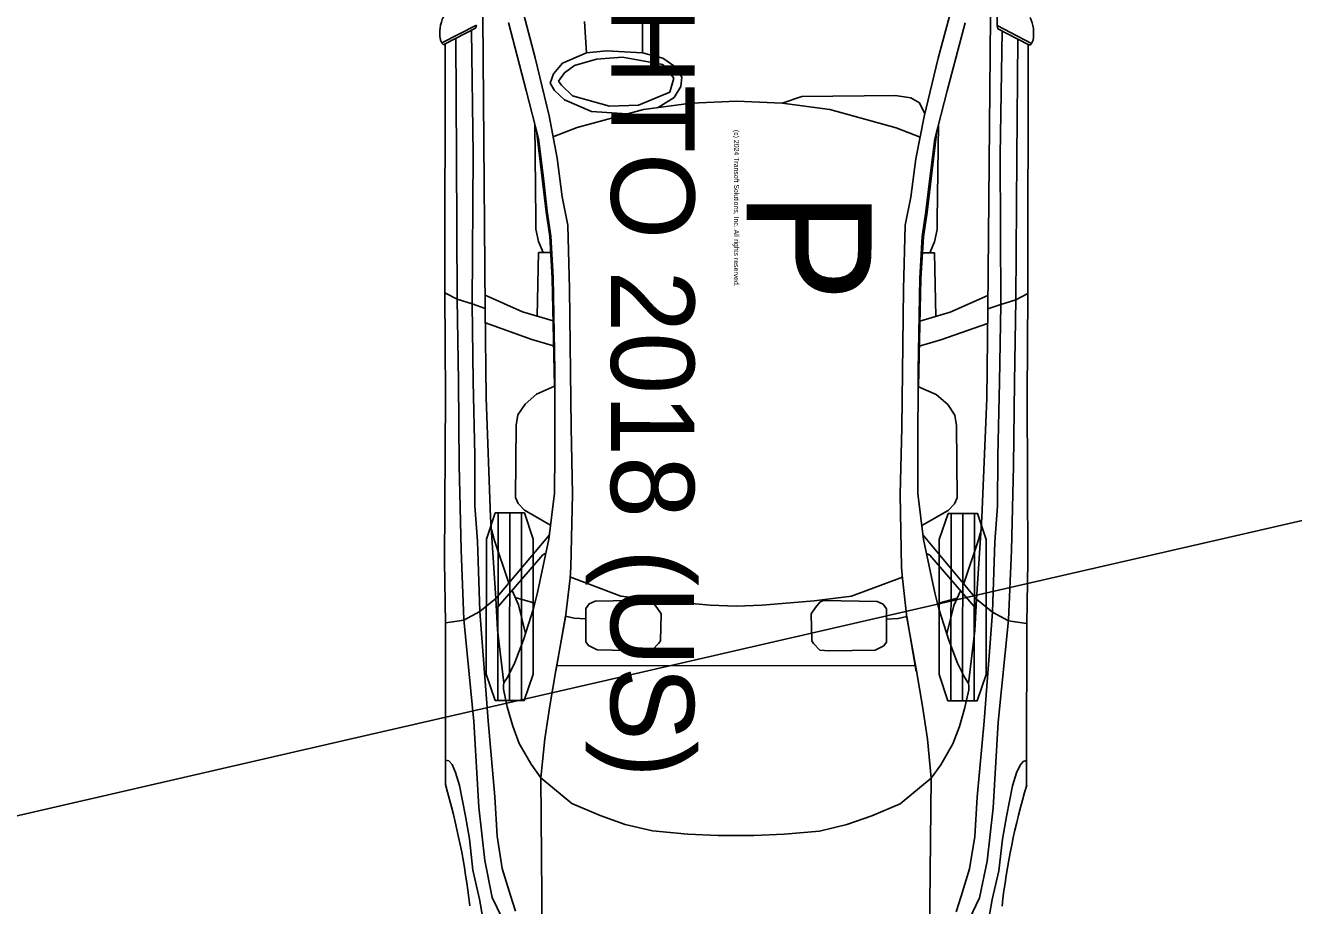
# Model space of a CAD drawing. Extents: x 17465868 to 18455672, y 7253752 to 7478845.
# Drawn here: x 18455110.2 to 18455125.43, y 7478342.35 to 7478352.92 of the extents above; entities that cross this region are included whole.
import ezdxf

# ---------------------------------------------------------------- set-up
doc = ezdxf.new("R2010")
doc.units = 0
doc.layers.add('Clinton 225 CL Girders', color=7, linetype='Continuous')
doc.layers.add('Dallas 126 CL Girder', color=7, linetype='Continuous')

msp = doc.modelspace()

# ---------------------------------------------------------------- linework, layer by layer
at = {"layer": 'Clinton 225 CL Girders'}
for p, q in [((18455116.144, 7478353.217), (18455116.324, 7478352.533)), ((18455121.345, 7478353.212), (18455121.164, 7478352.528)), ((18455115.697, 7478353.028), (18455115.726, 7478349.524)), ((18455116.217, 7478352.143), (18455116.004, 7478352.959)), ((18455116.94, 7478352.593), (18455116.917, 7478352.97)), ((18455117.615, 7478352.995), (18455117.615, 7478352.593)), ((18455121.792, 7478353.022), (18455121.757, 7478349.519)), ((18455121.87, 7478353.033), (18455121.87, 7478352.921)), ((18455115.204, 7478352.712), (18455115.619, 7478352.927)), ((18455115.61, 7478352.888), (18455115.244, 7478352.701)), ((18455115.58, 7478351.371), (18455115.56, 7478352.863)), ((18455115.619, 7478352.927), (18455115.61, 7478352.888)), ((18455121.485, 7478352.953), (18455121.271, 7478352.138)), ((18455121.87, 7478352.921), (18455121.879, 7478352.882)), ((18455122.285, 7478352.706), (18455121.87, 7478352.921)), ((18455121.879, 7478352.882), (18455122.244, 7478352.694)), ((18455121.906, 7478351.365), (18455121.929, 7478352.857)), ((18455115.186, 7478352.753), (18455115.204, 7478352.712)), ((18455115.207, 7478352.706), (18455115.213, 7478352.7)), ((18455115.244, 7478352.701), (18455115.241, 7478349.712)), ((18455115.371, 7478352.765), (18455115.38, 7478351.338)), ((18455122.106, 7478351.332), (18455122.118, 7478352.759)), ((18455122.241, 7478349.705), (18455122.244, 7478352.694)), ((18455122.275, 7478352.693), (18455122.281, 7478352.7)), ((18455122.285, 7478352.706), (18455122.302, 7478352.746)), ((18455116.324, 7478352.533), (18455116.491, 7478351.836)), ((18455116.651, 7478352.468), (18455116.94, 7478352.593)), ((18455116.796, 7478352.443), (18455117.061, 7478352.518)), ((18455116.94, 7478352.593), (18455117.181, 7478352.618)), ((18455117.061, 7478352.518), (18455117.374, 7478352.543)), ((18455117.181, 7478352.618), (18455117.615, 7478352.593)), ((18455117.374, 7478352.543), (18455117.856, 7478352.454)), ((18455117.615, 7478352.593), (18455117.856, 7478352.529)), ((18455117.856, 7478352.529), (18455118, 7478352.429)), ((18455121.164, 7478352.528), (18455120.996, 7478351.831)), ((18455116.543, 7478352.342), (18455116.651, 7478352.468)), ((18455116.603, 7478352.254), (18455116.675, 7478352.355)), ((18455116.675, 7478352.355), (18455116.796, 7478352.443)), ((18455117.856, 7478352.454), (18455117.988, 7478352.291)), ((18455118, 7478352.429), (18455118.084, 7478352.303)), ((18455116.506, 7478352.229), (18455116.543, 7478352.342)), ((18455116.555, 7478352.141), (18455116.506, 7478352.229)), ((18455116.639, 7478352.204), (18455116.603, 7478352.254)), ((18455116.771, 7478352.078), (18455116.639, 7478352.204)), ((18455117.988, 7478352.291), (18455117.942, 7478352.123)), ((18455118.084, 7478352.303), (18455118.072, 7478352.19)), ((18455116.363, 7478351.564), (18455116.217, 7478352.143)), ((18455116.675, 7478352.028), (18455116.555, 7478352.141)), ((18455117.217, 7478351.952), (18455116.771, 7478352.078)), ((18455117.942, 7478352.123), (18455117.566, 7478351.964)), ((18455117.995, 7478352.056), (18455117.803, 7478351.939)), ((18455118.072, 7478352.19), (18455117.995, 7478352.056)), ((18455119.289, 7478351.99), (18455119.526, 7478352.069)), ((18455119.526, 7478352.069), (18455120.646, 7478352.08)), ((18455120.646, 7478352.08), (18455120.834, 7478352.055)), ((18455120.834, 7478352.055), (18455120.94, 7478351.993)), ((18455121.271, 7478352.138), (18455121.123, 7478351.559)), ((18455117, 7478351.89), (18455116.675, 7478352.028)), ((18455117.624, 7478351.915), (18455116.829, 7478351.698)), ((18455117.566, 7478351.964), (18455117.217, 7478351.952)), ((18455118.199, 7478351.991), (18455117.624, 7478351.915)), ((18455118.744, 7478352.012), (18455118.199, 7478351.991)), ((18455119.289, 7478351.99), (18455118.744, 7478352.012)), ((18455119.863, 7478351.913), (18455119.289, 7478351.99)), ((18455120.657, 7478351.694), (18455119.863, 7478351.913)), ((18455120.94, 7478351.993), (18455121.003, 7478351.863)), ((18455116.491, 7478351.836), (18455116.59, 7478351.327)), ((18455117.431, 7478351.863), (18455117, 7478351.89)), ((18455120.996, 7478351.831), (18455120.896, 7478351.322)), ((18455116.333, 7478350.594), (18455116.319, 7478351.738)), ((18455116.455, 7478350.685), (18455116.339, 7478351.66)), ((18455116.829, 7478351.698), (18455116.547, 7478351.589)), ((18455120.947, 7478351.582), (18455120.657, 7478351.694)), ((18455121.029, 7478350.681), (18455121.148, 7478351.656)), ((18455121.151, 7478350.589), (18455121.167, 7478351.733)), ((18455116.423, 7478351.09), (18455116.363, 7478351.564)), ((18455121.123, 7478351.559), (18455121.062, 7478351.085)), ((18455115.38, 7478351.338), (18455115.389, 7478349.635)), ((18455115.568, 7478349.579), (18455115.58, 7478351.371)), ((18455116.59, 7478351.327), (18455116.65, 7478350.866)), ((18455120.896, 7478351.322), (18455120.835, 7478350.862)), ((18455121.915, 7478349.573), (18455121.906, 7478351.365)), ((18455122.094, 7478349.628), (18455122.106, 7478351.332)), ((18455116.469, 7478350.692), (18455116.423, 7478351.09)), ((18455121.062, 7478351.085), (18455121.015, 7478350.688)), ((18455116.65, 7478350.866), (18455116.718, 7478350.525)), ((18455120.835, 7478350.862), (18455120.767, 7478350.522)), ((18455116.499, 7478350.386), (18455116.455, 7478350.685)), ((18455116.512, 7478350.393), (18455116.469, 7478350.692)), ((18455121.015, 7478350.688), (18455120.972, 7478350.389)), ((18455120.985, 7478350.382), (18455121.029, 7478350.681)), ((18455116.333, 7478350.476), (18455116.333, 7478350.594)), ((18455116.718, 7478350.525), (18455116.737, 7478349.761)), ((18455121.151, 7478350.472), (18455121.151, 7478350.589)), ((18455116.364, 7478350.329), (18455116.333, 7478350.476)), ((18455116.529, 7478349.887), (18455116.499, 7478350.386)), ((18455116.541, 7478349.894), (18455116.512, 7478350.393)), ((18455120.767, 7478350.522), (18455120.746, 7478349.757)), ((18455120.972, 7478350.389), (18455120.942, 7478349.889)), ((18455120.954, 7478349.883), (18455120.985, 7478350.382)), ((18455121.12, 7478350.325), (18455121.151, 7478350.472)), ((18455116.42, 7478350.197), (18455116.364, 7478350.329)), ((18455121.064, 7478350.192), (18455121.12, 7478350.325)), ((18455116.349, 7478349.43), (18455116.364, 7478350.197)), ((18455116.364, 7478350.197), (18455116.507, 7478350.197)), ((18455121.12, 7478350.192), (18455120.977, 7478350.193)), ((18455121.133, 7478349.426), (18455121.12, 7478350.192)), ((18455116.555, 7478348.589), (18455116.529, 7478349.887)), ((18455116.56, 7478348.782), (18455116.541, 7478349.894)), ((18455116.737, 7478349.761), (18455116.755, 7478348.099)), ((18455120.942, 7478349.889), (18455120.921, 7478348.778)), ((18455120.926, 7478348.584), (18455120.954, 7478349.883)), ((18455115.241, 7478349.712), (18455115.389, 7478349.635)), ((18455115.241, 7478349.712), (18455115.248, 7478348.473)), ((18455115.389, 7478349.635), (18455115.404, 7478348.646)), ((18455115.389, 7478349.635), (18455115.568, 7478349.579)), ((18455115.725, 7478349.684), (18455116.174, 7478349.483)), ((18455120.746, 7478349.757), (18455120.725, 7478348.095)), ((18455121.758, 7478349.678), (18455121.308, 7478349.478)), ((18455122.094, 7478349.628), (18455121.915, 7478349.573)), ((18455122.077, 7478348.64), (18455122.094, 7478349.628)), ((18455122.241, 7478349.705), (18455122.094, 7478349.628)), ((18455122.232, 7478348.466), (18455122.241, 7478349.705)), ((18455115.581, 7478348.646), (18455115.568, 7478349.579)), ((18455115.568, 7478349.579), (18455115.726, 7478349.524)), ((18455115.726, 7478349.524), (18455115.736, 7478348.449)), ((18455116.174, 7478349.483), (18455116.539, 7478349.373)), ((18455121.308, 7478349.478), (18455120.943, 7478349.369)), ((18455121.757, 7478349.519), (18455121.745, 7478348.443)), ((18455121.915, 7478349.573), (18455121.757, 7478349.519)), ((18455121.9, 7478348.64), (18455121.915, 7478349.573)), ((18455115.727, 7478349.349), (18455116.286, 7478349.151)), ((18455121.755, 7478349.344), (18455121.196, 7478349.146)), ((18455116.286, 7478349.151), (18455116.545, 7478349.075)), ((18455121.196, 7478349.146), (18455120.936, 7478349.071)), ((18455116.559, 7478347.783), (18455116.56, 7478348.782)), ((18455120.921, 7478348.778), (18455120.92, 7478347.779)), ((18455115.404, 7478348.646), (18455115.414, 7478347.641)), ((18455115.602, 7478347.756), (18455115.581, 7478348.646)), ((18455116.341, 7478348.494), (18455116.555, 7478348.589)), ((18455121.14, 7478348.49), (18455120.926, 7478348.584)), ((18455121.877, 7478347.75), (18455121.9, 7478348.64)), ((18455122.065, 7478347.634), (18455122.077, 7478348.64)), ((18455115.248, 7478348.473), (18455115.235, 7478346.486)), ((18455115.736, 7478348.449), (18455115.79, 7478347.017)), ((18455116.203, 7478348.373), (18455116.341, 7478348.494)), ((18455121.278, 7478348.369), (18455121.14, 7478348.49)), ((18455121.745, 7478348.443), (18455121.688, 7478347.011)), ((18455122.241, 7478346.479), (18455122.232, 7478348.466)), ((18455116.095, 7478348.121), (18455116.118, 7478348.245)), ((18455116.118, 7478348.245), (18455116.203, 7478348.373)), ((18455121.362, 7478348.24), (18455121.278, 7478348.369)), ((18455121.384, 7478348.116), (18455121.362, 7478348.24)), ((18455116.089, 7478347.254), (18455116.095, 7478348.121)), ((18455116.755, 7478348.099), (18455116.773, 7478347.294)), ((18455120.725, 7478348.095), (18455120.705, 7478347.29)), ((18455121.389, 7478347.249), (18455121.384, 7478348.116)), ((18455116.558, 7478347.304), (18455116.559, 7478347.783)), ((18455115.414, 7478347.641), (18455115.435, 7478346.624)), ((18455115.602, 7478347.155), (18455115.602, 7478347.756)), ((18455120.92, 7478347.779), (18455120.92, 7478347.3)), ((18455121.876, 7478347.149), (18455121.877, 7478347.75)), ((18455122.042, 7478346.618), (18455122.065, 7478347.634)), ((18455116.12, 7478347.182), (18455116.089, 7478347.254)), ((18455116.197, 7478347.102), (18455116.12, 7478347.182)), ((18455116.489, 7478346.754), (18455116.558, 7478347.304)), ((18455116.773, 7478347.294), (18455116.753, 7478346.417)), ((18455120.705, 7478347.29), (18455120.724, 7478346.413)), ((18455120.92, 7478347.3), (18455120.988, 7478346.749)), ((18455121.281, 7478347.097), (18455121.358, 7478347.177)), ((18455121.358, 7478347.177), (18455121.389, 7478347.249)), ((18455115.634, 7478346.728), (18455115.602, 7478347.155)), ((18455115.88, 7478347.067), (18455115.877, 7478344.817)), ((18455116.02, 7478347.067), (18455116.018, 7478344.817)), ((18455116.161, 7478347.067), (18455116.159, 7478344.817)), ((18455116.51, 7478346.92), (18455116.197, 7478347.102)), ((18455120.967, 7478346.916), (18455121.281, 7478347.097)), ((18455121.317, 7478347.062), (18455121.315, 7478344.812)), ((18455121.458, 7478347.062), (18455121.456, 7478344.812)), ((18455121.598, 7478347.062), (18455121.596, 7478344.812)), ((18455121.843, 7478346.722), (18455121.876, 7478347.149)), ((18455115.79, 7478347.017), (18455115.852, 7478346.04)), ((18455121.688, 7478347.011), (18455121.623, 7478346.034)), ((18455115.661, 7478345.883), (18455115.634, 7478346.728)), ((18455115.831, 7478346.748), (18455115.799, 7478346.867)), ((18455116.007, 7478346.224), (18455115.831, 7478346.748)), ((18455115.852, 7478346.04), (18455116.496, 7478346.806)), ((18455116.352, 7478346.112), (18455116.489, 7478346.754)), ((18455121.623, 7478346.034), (18455120.981, 7478346.802)), ((18455120.988, 7478346.749), (18455121.124, 7478346.107)), ((18455121.469, 7478346.219), (18455121.646, 7478346.743)), ((18455121.646, 7478346.743), (18455121.678, 7478346.861)), ((18455121.814, 7478345.877), (18455121.843, 7478346.722)), ((18455115.435, 7478346.624), (18455115.47, 7478345.788)), ((18455116.416, 7478346.564), (18455115.859, 7478345.921)), ((18455116.453, 7478346.583), (18455116.416, 7478346.564)), ((18455121.024, 7478346.579), (18455121.061, 7478346.56)), ((18455122.005, 7478345.782), (18455122.042, 7478346.618)), ((18455115.235, 7478346.486), (18455115.249, 7478345.747)), ((18455116.753, 7478346.417), (18455116.743, 7478346.285)), ((18455120.724, 7478346.413), (18455120.733, 7478346.281)), ((18455121.061, 7478346.56), (18455121.617, 7478345.916)), ((18455122.227, 7478345.74), (18455122.241, 7478346.479)), ((18455116.743, 7478346.285), (18455116.687, 7478345.814)), ((18455116.741, 7478346.299), (18455117.354, 7478346.07)), ((18455120.122, 7478346.067), (18455120.735, 7478346.295)), ((18455120.733, 7478346.281), (18455120.788, 7478345.81)), ((18455116.047, 7478346.138), (18455116.126, 7478345.963)), ((18455116.304, 7478345.92), (18455116.352, 7478346.112)), ((18455121.124, 7478346.107), (18455121.172, 7478345.916)), ((18455121.429, 7478346.133), (18455121.35, 7478345.958)), ((18455115.661, 7478345.883), (18455115.852, 7478346.04)), ((18455115.852, 7478346.04), (18455115.872, 7478345.662)), ((18455116.086, 7478346.051), (18455116.32, 7478345.985)), ((18455116.126, 7478345.963), (18455116.207, 7478345.621)), ((18455116.933, 7478345.921), (18455116.974, 7478345.975)), ((18455116.974, 7478345.975), (18455117.047, 7478346.008)), ((18455117.047, 7478346.008), (18455117.691, 7478346.02)), ((18455117.354, 7478346.07), (18455117.801, 7478346.015)), ((18455117.691, 7478346.02), (18455117.733, 7478345.998)), ((18455117.733, 7478345.998), (18455117.785, 7478345.933)), ((18455117.801, 7478346.015), (18455118.425, 7478345.961)), ((18455118.425, 7478345.961), (18455118.738, 7478345.949)), ((18455118.738, 7478345.949), (18455119.05, 7478345.96)), ((18455119.05, 7478345.96), (18455119.674, 7478346.014)), ((18455119.674, 7478346.014), (18455120.122, 7478346.067)), ((18455119.743, 7478345.996), (18455119.691, 7478345.931)), ((18455119.784, 7478346.018), (18455119.743, 7478345.996)), ((18455120.429, 7478346.004), (18455119.784, 7478346.018)), ((18455120.502, 7478345.972), (18455120.429, 7478346.004)), ((18455120.543, 7478345.917), (18455120.502, 7478345.972)), ((18455121.39, 7478346.046), (18455121.156, 7478345.98)), ((18455121.35, 7478345.958), (18455121.268, 7478345.616)), ((18455121.623, 7478346.034), (18455121.603, 7478345.657)), ((18455121.814, 7478345.877), (18455121.623, 7478346.034)), ((18455115.47, 7478345.778), (18455115.661, 7478345.883)), ((18455115.76, 7478344.571), (18455115.661, 7478345.883)), ((18455116.183, 7478345.545), (18455116.304, 7478345.92)), ((18455116.687, 7478345.814), (18455116.573, 7478345.175)), ((18455116.69, 7478345.827), (18455116.574, 7478345.169)), ((18455116.792, 7478345.803), (18455116.69, 7478345.827)), ((18455116.933, 7478345.796), (18455116.792, 7478345.803)), ((18455116.933, 7478345.519), (18455116.933, 7478345.921)), ((18455117.785, 7478345.933), (18455117.837, 7478345.857)), ((18455117.837, 7478345.857), (18455117.828, 7478345.532)), ((18455119.691, 7478345.931), (18455119.638, 7478345.856)), ((18455119.638, 7478345.856), (18455119.647, 7478345.53)), ((18455120.542, 7478345.516), (18455120.543, 7478345.917)), ((18455120.684, 7478345.8), (18455120.785, 7478345.824)), ((18455120.785, 7478345.824), (18455120.9, 7478345.165)), ((18455120.788, 7478345.81), (18455120.901, 7478345.171)), ((18455121.172, 7478345.916), (18455121.292, 7478345.54)), ((18455121.713, 7478344.565), (18455121.814, 7478345.877)), ((18455122.005, 7478345.772), (18455121.814, 7478345.877)), ((18455115.249, 7478345.747), (18455115.247, 7478344.099)), ((18455115.249, 7478345.747), (18455115.389, 7478345.768)), ((18455115.389, 7478345.768), (18455115.47, 7478345.778)), ((18455115.47, 7478345.788), (18455115.589, 7478344.561)), ((18455115.872, 7478345.662), (18455115.949, 7478345.027)), ((18455120.543, 7478345.792), (18455120.684, 7478345.8)), ((18455121.603, 7478345.657), (18455121.525, 7478345.021)), ((18455121.884, 7478344.555), (18455122.005, 7478345.782)), ((18455122.086, 7478345.761), (18455122.005, 7478345.772)), ((18455122.227, 7478345.74), (18455122.086, 7478345.761)), ((18455122.227, 7478345.74), (18455122.225, 7478344.093)), ((18455122.225, 7478344.093), (18455122.227, 7478345.74)), ((18455116.081, 7478345.27), (18455116.183, 7478345.545)), ((18455116.965, 7478345.476), (18455116.933, 7478345.519)), ((18455117.807, 7478345.499), (18455117.734, 7478345.423)), ((18455117.828, 7478345.532), (18455117.807, 7478345.499)), ((18455119.647, 7478345.53), (18455119.668, 7478345.498)), ((18455120.51, 7478345.473), (18455120.542, 7478345.516)), ((18455121.292, 7478345.54), (18455121.394, 7478345.264)), ((18455117.069, 7478345.422), (18455116.965, 7478345.476)), ((18455117.62, 7478345.412), (18455117.069, 7478345.422)), ((18455117.734, 7478345.423), (18455117.62, 7478345.412)), ((18455119.668, 7478345.498), (18455119.741, 7478345.421)), ((18455119.741, 7478345.421), (18455119.855, 7478345.41)), ((18455119.855, 7478345.41), (18455120.406, 7478345.419)), ((18455120.406, 7478345.419), (18455120.51, 7478345.473)), ((18455115.997, 7478345.101), (18455116.081, 7478345.27)), ((18455120.891, 7478345.231), (18455116.584, 7478345.235)), ((18455121.394, 7478345.264), (18455121.477, 7478345.095)), ((18455115.949, 7478345.026), (18455115.997, 7478345.101)), ((18455116.573, 7478345.175), (18455116.5, 7478344.75)), ((18455120.901, 7478345.171), (18455120.973, 7478344.745)), ((18455121.477, 7478345.095), (18455121.525, 7478345.02)), ((18455115.943, 7478345), (18455115.949, 7478345.026)), ((18455115.943, 7478344.95), (18455115.943, 7478345)), ((18455115.99, 7478344.738), (18455115.943, 7478344.95)), ((18455121.531, 7478344.945), (18455121.483, 7478344.732)), ((18455121.525, 7478345.02), (18455121.531, 7478344.995)), ((18455121.531, 7478344.995), (18455121.531, 7478344.945)), ((18455116.056, 7478344.506), (18455115.99, 7478344.738)), ((18455116.5, 7478344.75), (18455116.44, 7478344.355)), ((18455120.973, 7478344.745), (18455121.033, 7478344.351)), ((18455121.483, 7478344.732), (18455121.417, 7478344.501)), ((18455115.589, 7478344.561), (18455115.649, 7478343.532)), ((18455115.84, 7478343.658), (18455115.76, 7478344.571)), ((18455116.134, 7478344.299), (18455116.056, 7478344.506)), ((18455121.417, 7478344.501), (18455121.339, 7478344.294)), ((18455121.631, 7478343.653), (18455121.713, 7478344.565)), ((18455121.822, 7478343.526), (18455121.884, 7478344.555)), ((18455116.278, 7478344.049), (18455116.134, 7478344.299)), ((18455116.44, 7478344.355), (18455116.392, 7478343.886)), ((18455121.033, 7478344.351), (18455121.08, 7478343.881)), ((18455121.339, 7478344.294), (18455121.194, 7478344.044)), ((18455115.287, 7478344.089), (18455115.247, 7478344.099)), ((18455115.247, 7478344.099), (18455115.247, 7478343.805)), ((18455115.327, 7478344.047), (18455115.287, 7478344.089)), ((18455115.368, 7478343.952), (18455115.327, 7478344.047)), ((18455116.392, 7478343.886), (18455116.278, 7478344.049)), ((18455121.194, 7478344.044), (18455121.08, 7478343.881)), ((18455122.145, 7478344.04), (18455122.104, 7478343.946)), ((18455122.185, 7478344.082), (18455122.145, 7478344.04)), ((18455122.225, 7478344.093), (18455122.185, 7478344.082)), ((18455122.225, 7478343.798), (18455122.225, 7478344.093)), ((18455115.418, 7478343.795), (18455115.368, 7478343.952)), ((18455116.392, 7478343.886), (18455116.412, 7478341.809)), ((18455116.765, 7478343.577), (18455116.392, 7478343.886)), ((18455121.08, 7478343.881), (18455120.706, 7478343.573)), ((18455121.08, 7478343.881), (18455121.056, 7478341.804)), ((18455122.104, 7478343.946), (18455122.054, 7478343.789)), ((18455115.488, 7478343.427), (18455115.418, 7478343.795)), ((18455122.054, 7478343.789), (18455121.983, 7478343.421)), ((18455115.649, 7478343.532), (18455115.719, 7478342.892)), ((18455115.87, 7478343.186), (18455115.84, 7478343.658)), ((18455117.104, 7478343.432), (18455116.765, 7478343.577)), ((18455120.706, 7478343.573), (18455120.367, 7478343.429)), ((18455121.601, 7478343.18), (18455121.631, 7478343.653)), ((18455121.751, 7478342.886), (18455121.822, 7478343.526)), ((18455115.538, 7478343.155), (18455115.488, 7478343.427)), ((18455117.405, 7478343.327), (18455117.104, 7478343.432)), ((18455120.367, 7478343.429), (18455120.065, 7478343.325)), ((18455121.983, 7478343.421), (18455121.933, 7478343.149)), ((18455117.732, 7478343.248), (18455117.405, 7478343.327)), ((18455118.159, 7478343.209), (18455117.732, 7478343.248)), ((18455119.739, 7478343.246), (18455119.312, 7478343.208)), ((18455120.065, 7478343.325), (18455119.739, 7478343.246)), ((18455115.578, 7478342.777), (18455115.538, 7478343.155)), ((18455115.93, 7478342.797), (18455115.87, 7478343.186)), ((18455118.523, 7478343.195), (18455118.159, 7478343.209)), ((18455118.735, 7478343.195), (18455118.523, 7478343.195)), ((18455118.948, 7478343.195), (18455118.735, 7478343.195)), ((18455119.312, 7478343.208), (18455118.948, 7478343.195)), ((18455121.54, 7478342.792), (18455121.601, 7478343.18)), ((18455121.933, 7478343.149), (18455121.892, 7478342.771)), ((18455115.658, 7478342.43), (18455115.578, 7478342.777)), ((18455115.719, 7478342.892), (18455115.809, 7478342.451)), ((18455116.03, 7478342.472), (18455115.93, 7478342.797)), ((18455121.439, 7478342.467), (18455121.54, 7478342.792)), ((18455121.66, 7478342.446), (18455121.751, 7478342.886)), ((18455121.892, 7478342.771), (18455121.811, 7478342.425)), ((18455116.09, 7478342.283), (18455116.03, 7478342.472)), ((18455121.379, 7478342.278), (18455121.439, 7478342.467)), ((18455115.697, 7478342.202), (18455115.658, 7478342.43)), ((18455115.809, 7478342.451), (18455115.929, 7478342.199)), ((18455121.539, 7478342.194), (18455121.66, 7478342.446)), ((18455121.811, 7478342.425), (18455121.772, 7478342.197))]:
    msp.add_line(p, q, dxfattribs=at)
for points in [[(18455115.845, 7478347.067), (18455116.196, 7478347.067), (18455116.301, 7478346.752), (18455116.3, 7478345.132), (18455116.194, 7478344.817), (18455115.843, 7478344.817), (18455115.737, 7478345.132), (18455115.739, 7478346.752)], [(18455121.282, 7478347.062), (18455121.633, 7478347.062), (18455121.739, 7478346.747), (18455121.737, 7478345.127), (18455121.631, 7478344.812), (18455121.28, 7478344.812), (18455121.175, 7478345.127), (18455121.176, 7478346.747)]]:
    msp.add_lwpolyline(points, close=True, dxfattribs=at)
for centre, radius, start, end in [((18455115.625, 7478352.833), 0.445, 154.2176, 190.3459), ((18455121.864, 7478352.827), 0.445, 349.5453, 25.6736), ((18455115.221, 7478352.72), 0.019, 202.7707, 223.8405), ((18455115.229, 7478352.718), 0.0236, 230.107, 311.6042), ((18455078.663, 7478317.74), 50.578, 43.72593027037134, 43.72593071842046), ((18455122.26, 7478352.712), 0.0236, 228.287, 309.7842), ((18455122.268, 7478352.713), 0.0183, 315.6007, 337.5705), ((18455107.055, 7478341.397), 8.538, 6.4143, 16.3778), ((18455130.412, 7478341.375), 8.538, 163.5134, 173.477)]:
    msp.add_arc(centre, radius, start, end, dxfattribs=at)
at = {"layer": 'Dallas 126 CL Girder'}
for radius in [15064.793, 15052.793, 15040.793, 15028.793, 15018.793, 14988.793, 14978.793, 14966.793, 14954.793, 14942.793]:
    msp.add_arc((18458471.778, 7463759.052), radius, 101.0668789, 104.665109, dxfattribs=at)

# ---------------------------------------------------------------- texts
at = {"layer": 'Clinton 225 CL Girders'}
for s, height, p in [('AASHTO 2018 (US)', 1, (18455117.242, 7478355.852)), ('(c) 2024 Transoft Solutions, Inc. All rights reserved.', 0.06, (18455118.713, 7478351.668)), ('P', 1.5, (18455118.863, 7478350.939))]:
    msp.add_text(s, height=height, rotation=269.9456, dxfattribs=at).set_placement(p)

doc.saveas('drawing.dxf')
